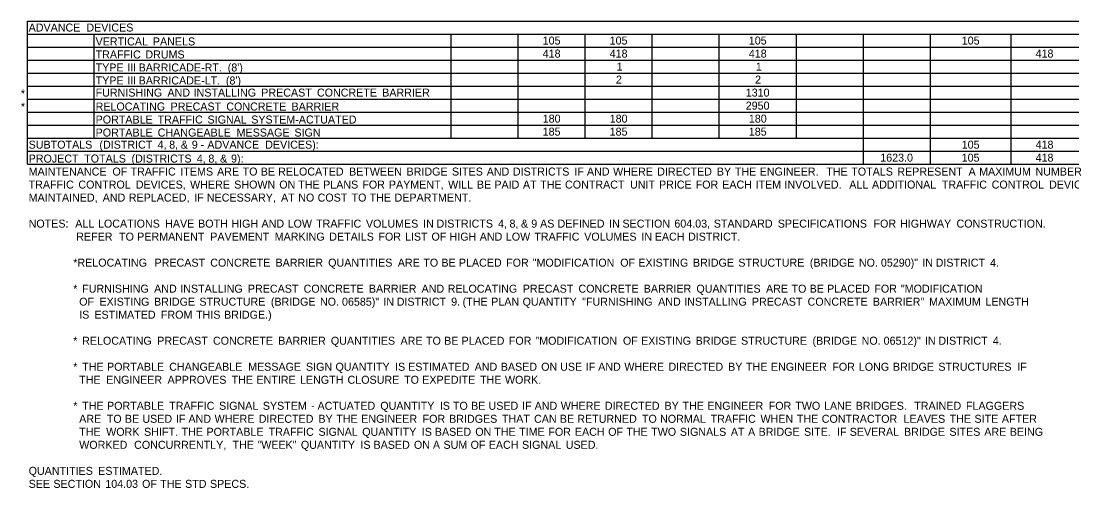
# Model space of a CAD drawing. Extents: x 544420 to 1930787, y -1947044 to 596640.
# Drawn here: x 544421 to 545209, y -1946986 to -1946636 of the extents above; entities that cross this region are included whole.
import ezdxf

# ---------------------------------------------------------------- set-up
doc = ezdxf.new("R2010")
doc.units = 0
doc.layers.add('Default', color=7, linetype='Continuous')

msp = doc.modelspace()

# ---------------------------------------------------------------- linework, layer by layer
at = {"layer": 'Default'}
for p, q in [((544425.9, -1946636.01), (545626.13, -1946636.01)), ((544425.9, -1946636.01), (545626.13, -1946636.01)), ((544425.9, -1946743.26), (544425.9, -1946636.01)), ((544425.9, -1946743.26), (544425.9, -1946636.01)), ((544425.9, -1946645.76), (545626.13, -1946645.76)), ((544476.12, -1946684.76), (544476.12, -1946645.76)), ((544476.12, -1946723.76), (544476.12, -1946645.76)), ((544743.75, -1946723.76), (544743.75, -1946645.76)), ((544743.75, -1946723.76), (544743.75, -1946645.76)), ((544793.97, -1946723.76), (544793.97, -1946645.76)), ((544793.97, -1946723.76), (544793.97, -1946645.76)), ((544844.18, -1946723.76), (544844.18, -1946645.76)), ((544844.18, -1946723.76), (544844.18, -1946645.76)), ((544894.39, -1946723.76), (544894.39, -1946645.76)), ((544894.39, -1946723.76), (544894.39, -1946645.76)), ((544944.6, -1946723.76), (544944.6, -1946645.76)), ((544944.6, -1946723.76), (544944.6, -1946645.76)), ((545002.62, -1946723.76), (545002.62, -1946645.76)), ((545052.83, -1946743.26), (545052.83, -1946645.76)), ((545052.83, -1946743.26), (545052.83, -1946645.76)), ((545103.04, -1946743.26), (545103.04, -1946645.76)), ((545103.04, -1946743.26), (545103.04, -1946645.76)), ((545163.49, -1946743.26), (545163.49, -1946645.76)), ((545163.49, -1946743.26), (545163.49, -1946645.76)), ((544425.9, -1946655.51), (545626.13, -1946655.51)), ((544425.9, -1946665.26), (545626.13, -1946665.26)), ((544425.9, -1946675.01), (545626.13, -1946675.01)), ((544425.9, -1946684.76), (545626.13, -1946684.76)), ((544425.9, -1946694.51), (544476.12, -1946694.51)), ((544425.9, -1946694.51), (545626.13, -1946694.51)), ((544476.12, -1946723.76), (544476.12, -1946694.51)), ((544743.75, -1946694.51), (544944.6, -1946694.51)), ((544944.6, -1946694.51), (545002.62, -1946694.51)), ((545002.62, -1946694.51), (545310.23, -1946694.51)), ((544425.9, -1946704.26), (545626.13, -1946704.26)), ((544425.9, -1946714.01), (545626.13, -1946714.01)), ((545002.62, -1946723.76), (545002.62, -1946714.01)), ((544425.9, -1946723.76), (545002.62, -1946723.76)), ((544425.9, -1946723.76), (545626.13, -1946723.76)), ((545002.62, -1946723.76), (545626.13, -1946723.76)), ((544425.9, -1946733.51), (545626.13, -1946733.51)), ((544425.9, -1946743.26), (545626.13, -1946743.26))]:
    msp.add_line(p, q, dxfattribs=at)

# ---------------------------------------------------------------- texts
for s, p in [('ADVANCE', (544426.88, -1946643.88)), (' DEVICES', (544467.92, -1946643.88)), ('105', (544812.25, -1946653.63)), ('105', (544862.46, -1946653.63)), ('105', (544966.79, -1946653.63)), ('105', (545126.44, -1946653.63)), ('VERTICAL', (544477.09, -1946654.31)), (' PANELS', (544517.79, -1946654.31)), ('TRAFFIC', (544477.09, -1946664.06)), (' DRUMS', (544512.15, -1946664.06)), ('418', (544812.27, -1946663.38)), ('418', (544862.48, -1946663.38)), ('418', (544966.81, -1946663.38)), ('418', (545181.79, -1946663.38)), ('TYPE', (544477.09, -1946673.81)), (' III', (544498.54, -1946673.81)), (' BARRICADE-RT.', (544507.11, -1946673.81)), (" (8')", (544573.91, -1946673.81)), ('1', (544867.73, -1946673.13)), ('1', (544972.05, -1946673.13)), ('TYPE', (544477.09, -1946683.56)), (' III', (544498.54, -1946683.56)), (' BARRICADE-LT.', (544507.11, -1946683.56)), (" (8')", (544572.52, -1946683.56)), ('2', (544867.18, -1946682.88)), ('2', (544971.5, -1946682.88)), ('*', (544421.03, -1946693.31)), ('FURNISHING', (544477.09, -1946692.63)), (' AND', (544528.73, -1946692.63)), (' INSTALLING', (544548.31, -1946692.63)), (' PRECAST', (544599.03, -1946692.63)), (' CONCRETE', (544640.79, -1946692.63)), (' BARRIER', (544689.72, -1946692.63)), ('1310', (544964.49, -1946692.63)), ('*', (544421.03, -1946703.06)), ('RELOCATING', (544477.09, -1946703.06)), (' PRECAST', (544531.07, -1946703.06)), (' CONCRETE', (544572.83, -1946703.06)), (' BARRIER', (544621.76, -1946703.06)), ('2950', (544964.49, -1946702.38)), ('PORTABLE', (544477.09, -1946712.81)), (' TRAFFIC', (544521.37, -1946712.81)), (' SIGNAL', (544558.76, -1946712.81)), (' SYSTEM-ACTUATED', (544591.54, -1946712.81)), ('180', (544812.28, -1946712.13)), ('180', (544862.5, -1946712.13)), ('180', (544966.82, -1946712.13)), ('PORTABLE', (544477.09, -1946722.56)), (' CHANGEABLE', (544521.37, -1946722.56)), (' MESSAGE', (544580.56, -1946722.56)), (' SIGN', (544623.91, -1946722.56)), ('185', (544812.25, -1946721.88)), ('185', (544862.46, -1946721.88)), ('185', (544966.79, -1946721.88)), ('SUBTOTALS', (544426.88, -1946731.63)), (' (DISTRICT', (544477.71, -1946731.63)), (' 4,', (544521.31, -1946731.63)), (' 8,', (544530.02, -1946731.63)), (' &', (544538.73, -1946731.63)), (' 9', (544546.98, -1946731.63)), (' ADVANCE', (544558.63, -1946731.63)), (' DEVICES):', (544602, -1946731.63)), ('105', (545126.4, -1946731.63)), ('418', (545181.8, -1946731.63)), (' -', (544553.57, -1946731.63)), ('PROJECT', (544426.88, -1946742.06)), (' TOTALS', (544466.3, -1946742.06)), (' (DISTRICTS', (544501.76, -1946742.06)), (' 4,', (544550.71, -1946742.06)), (' 8,', (544559.42, -1946742.06)), (' &', (544568.14, -1946742.06)), (' 9):', (544576.38, -1946742.06)), ('1623.0', (545065.33, -1946741.38)), ('105', (545126.4, -1946741.38)), ('418', (545181.8, -1946741.38)), ('MAINTENANCE', (544426.88, -1946751.81)), (' OF', (544487.46, -1946751.81)), (' TRAFFIC', (544501.04, -1946751.81)), (' ITEMS', (544538.43, -1946751.81)), (' ARE', (544565.94, -1946751.81)), (' TO', (544585.06, -1946751.81)), (' BE', (544598.66, -1946751.81)), (' RELOCATED', (544611.72, -1946751.81)), (' BETWEEN', (544664.85, -1946751.81)), (' BRIDGE', (544707.95, -1946751.81)), (' SITES', (544741.98, -1946751.81)), (' AND', (544768.09, -1946751.81)), (' DISTRICTS', (544787.67, -1946751.81)), (' IF', (544833.81, -1946751.81)), (' AND', (544843.21, -1946751.81)), (' WHERE', (544862.79, -1946751.81)), (' DIRECTED', (544895.88, -1946751.81)), (' BY', (544940.61, -1946751.81)), (' THE', (544954.06, -1946751.81)), (' ENGINEER.', (544972.71, -1946751.81)), ('  THE', (545020.43, -1946751.81)), (' TOTALS', (545041.4, -1946751.81)), (' REPRESENT', (545075.9, -1946751.81)), (' A', (545129.31, -1946751.81)), (' MAXIMUM', (545137.25, -1946751.81)), (' NUMBER', (545179.46, -1946751.81)), ('TRAFFIC', (544426.88, -1946761.56)), (' CONTROL', (544461.94, -1946761.56)), (' DEVICES,', (544504.96, -1946761.56)), (' WHERE', (544545.68, -1946761.56)), (' SHOWN', (544578.77, -1946761.56)), (' ON', (544612.55, -1946761.56)), (' THE', (544626.76, -1946761.56)), (' PLANS', (544645.41, -1946761.56)), (' FOR', (544674.8, -1946761.56)), (' PAYMENT,', (544694.71, -1946761.56)), (' WILL', (544739.15, -1946761.56)), (' BE', (544760.74, -1946761.56)), (' PAID', (544773.8, -1946761.56)), (' AT', (544795.25, -1946761.56)), (' THE', (544808.13, -1946761.56)), (' CONTRACT', (544826.78, -1946761.56)), (' UNIT', (544875.51, -1946761.56)), (' PRICE', (544897.23, -1946761.56)), (' FOR', (544924.73, -1946761.56)), (' EACH', (544944.64, -1946761.56)), (' ITEM', (544969.59, -1946761.56)), (' INVOLVED.', (544991.31, -1946761.56)), ('  ALL', (545037.64, -1946761.56)), (' ADDITIONAL', (545056.91, -1946761.56)), (' TRAFFIC', (545109.25, -1946761.56)), (' CONTROL', (545146.64, -1946761.56)), (' DEVICES', (545189.66, -1946761.56)), ('MAINTAINED,', (544426.88, -1946771.31)), (' AND', (544480.17, -1946771.31)), (' REPLACED,', (544499.75, -1946771.31)), (' IF', (544548.85, -1946771.31)), (' NECESSARY,', (544558.25, -1946771.31)), (' AT', (544613.88, -1946771.31)), (' NO', (544626.75, -1946771.31)), (' COST', (544641.28, -1946771.31)), (' TO', (544666.73, -1946771.31)), (' THE', (544680.33, -1946771.31)), (' DEPARTMENT.', (544698.98, -1946771.31)), ('NOTES:', (544426.88, -1946790.81)), ('  ALL', (544457.36, -1946790.81)), (' LOCATIONS', (544476.63, -1946790.81)), (' HAVE', (544526.97, -1946790.81)), (' BOTH', (544551.68, -1946790.81)), (' HIGH', (544576.62, -1946790.81)), (' AND', (544599.23, -1946790.81)), (' LOW', (544618.81, -1946790.81)), (' TRAFFIC', (544640.14, -1946790.81)), (' VOLUMES', (544677.53, -1946790.81)), (' IN', (544720.42, -1946790.81)), (' DISTRICTS', (544730.44, -1946790.81)), (' 4,', (544776.58, -1946790.81)), (' 8,', (544785.15, -1946790.81)), (' &', (544793.72, -1946790.81)), (' 9', (544801.45, -1946790.81)), (' AS', (544808.07, -1946790.81)), (' DEFINED', (544821.14, -1946790.81)), (' IN', (544859.82, -1946790.81)), (' SECTION', (544869.85, -1946790.81)), (' 604.03,', (544908.75, -1946790.81)), (' STANDARD', (544938.29, -1946790.81)), (' SPECIFICATIONS', (544986.29, -1946790.81)), (' FOR', (545058.06, -1946790.81)), (' HIGHWAY', (545077.97, -1946790.81)), (' CONSTRUCTION.', (545120.29, -1946790.81)), ('                REFER', (544426.88, -1946800.56)), (' TO', (544492.43, -1946800.56)), (' PERMANENT', (544506.02, -1946800.56)), (' PAVEMENT', (544560.82, -1946800.56)), (' MARKING', (544609.11, -1946800.56)), (' DETAILS', (544650.04, -1946800.56)), (' FOR', (544686.87, -1946800.56)), (' LIST', (544706.78, -1946800.56)), (' OF', (544726.64, -1946800.56)), (' HIGH', (544740.23, -1946800.56)), (' AND', (544762.84, -1946800.56)), (' LOW', (544782.42, -1946800.56)), (' TRAFFIC', (544803.74, -1946800.56)), (' VOLUMES', (544841.14, -1946800.56)), (' IN', (544884.02, -1946800.56)), (' EACH', (544894.05, -1946800.56)), (' DISTRICT.', (544918.99, -1946800.56)), ('               *RELOCATING', (544426.88, -1946820.06)), (' PRECAST', (544519.03, -1946820.06)), (' CONCRETE', (544560.8, -1946820.06)), (' BARRIER', (544609.72, -1946820.06)), (' QUANTITIES', (544649.21, -1946820.06)), (' ARE', (544701.41, -1946820.06)), (' TO', (544720.53, -1946820.06)), (' BE', (544734.12, -1946820.06)), (' PLACED', (544747.19, -1946820.06)), (' FOR', (544782.62, -1946820.06)), (' "MODIFICATION', (544802.53, -1946820.06)), (' OF', (544868.16, -1946820.06)), (' EXISTING', (544881.74, -1946820.06)), (' BRIDGE', (544922.68, -1946820.06)), (' STRUCTURE', (544956.7, -1946820.06)), (' (BRIDGE', (545010.29, -1946820.06)), (' NO.', (545047.1, -1946820.06)), (' 05290)"', (545063.6, -1946820.06)), (' IN', (545094.6, -1946820.06)), (' DISTRICT', (545104.63, -1946820.06)), (' 4.', (545145.44, -1946820.06)), ('               *', (544426.88, -1946839.56)), (' FURNISHING', (544464.76, -1946839.56)), (' AND', (544518.73, -1946839.56)), (' INSTALLING', (544538.31, -1946839.56)), (' PRECAST', (544589.03, -1946839.56)), (' CONCRETE', (544630.79, -1946839.56)), (' BARRIER', (544679.72, -1946839.56)), (' AND', (544719.21, -1946839.56)), (' RELOCATING', (544738.79, -1946839.56)), (' PRECAST', (544795.09, -1946839.56)), (' CONCRETE', (544836.85, -1946839.56)), (' BARRIER', (544885.78, -1946839.56)), (' QUANTITIES', (544925.27, -1946839.56)), (' ARE', (544977.47, -1946839.56)), (' TO', (544996.59, -1946839.56)), (' BE', (545010.18, -1946839.56)), (' PLACED', (545023.25, -1946839.56)), (' FOR', (545058.68, -1946839.56)), (' "MODIFICATION', (545078.59, -1946839.56)), ('                 OF', (544426.88, -1946849.31)), (' EXISTING', (544477.71, -1946849.31)), (' BRIDGE', (544518.64, -1946849.31)), (' STRUCTURE', (544552.67, -1946849.31)), (' (BRIDGE', (544606.25, -1946849.31)), (' NO.', (544643.07, -1946849.31)), (' 06585)"', (544659.57, -1946849.31)), (' IN', (544690.57, -1946849.31)), (' DISTRICT', (544700.59, -1946849.31)), (' 9.', (544741.41, -1946849.31)), (' (THE', (544749.99, -1946849.31)), (' PLAN', (544771.43, -1946849.31)), (' QUANTITY', (544794.97, -1946849.31)), (' "FURNISHING', (544839.63, -1946849.31)), (' AND', (544896.57, -1946849.31)), (' INSTALLING', (544916.15, -1946849.31)), (' PRECAST', (544966.87, -1946849.31)), (' CONCRETE', (545008.63, -1946849.31)), (' BARRIER"', (545057.56, -1946849.31)), (' MAXIMUM', (545099.74, -1946849.31)), (' LENGTH', (545141.96, -1946849.31)), (' BRIDGE.)', (544571.16, -1946859.06)), ('                 IS', (544426.88, -1946859.06)), (' ESTIMATED', (544473.93, -1946859.06)), (' FROM', (544523.79, -1946859.06)), (' THIS', (544550.17, -1946859.06)), ('               *', (544426.88, -1946878.56)), (' RELOCATING', (544464.76, -1946878.56)), (' PRECAST', (544521.07, -1946878.56)), (' CONCRETE', (544562.83, -1946878.56)), (' BARRIER', (544611.76, -1946878.56)), (' QUANTITIES', (544651.24, -1946878.56)), (' ARE', (544703.44, -1946878.56)), (' TO', (544722.56, -1946878.56)), (' BE', (544736.16, -1946878.56)), (' PLACED', (544749.22, -1946878.56)), (' FOR', (544784.65, -1946878.56)), (' "MODIFICATION', (544804.56, -1946878.56)), (' OF', (544870.19, -1946878.56)), (' EXISTING', (544883.78, -1946878.56)), (' BRIDGE', (544924.71, -1946878.56)), (' STRUCTURE', (544958.74, -1946878.56)), (' (BRIDGE', (545012.32, -1946878.56)), (' NO.', (545049.14, -1946878.56)), (' 06512)"', (545065.64, -1946878.56)), (' IN', (545096.64, -1946878.56)), (' DISTRICT', (545106.66, -1946878.56)), (' 4.', (545147.48, -1946878.56)), ('               *', (544426.88, -1946898.06)), (' THE', (544464.76, -1946898.06)), (' PORTABLE', (544483.41, -1946898.06)), (' CHANGEABLE', (544530.02, -1946898.06)), (' MESSAGE', (544589.21, -1946898.06)), (' SIGN', (544632.56, -1946898.06)), (' QUANTITY', (544654.7, -1946898.06)), (' IS', (544699.35, -1946898.06)), (' ESTIMATED', (544709.16, -1946898.06)), (' AND', (544759.02, -1946898.06)), (' BASED', (544778.61, -1946898.06)), (' ON', (544808.91, -1946898.06)), (' USE', (544823.13, -1946898.06)), (' IF', (544842.25, -1946898.06)), (' AND', (544851.64, -1946898.06)), (' WHERE', (544871.23, -1946898.06)), (' DIRECTED', (544904.31, -1946898.06)), (' BY', (544949.05, -1946898.06)), (' THE', (544962.5, -1946898.06)), (' ENGINEER', (544981.15, -1946898.06)), (' FOR', (545027.15, -1946898.06)), (' LONG', (545047.06, -1946898.06)), (' BRIDGE', (545072.62, -1946898.06)), (' STRUCTURES', (545106.65, -1946898.06)), (' IF', (545165.83, -1946898.06)), ('                 THE', (544426.88, -1946907.81)), (' ENGINEER', (544482.77, -1946907.81)), (' APPROVES', (544528.78, -1946907.81)), (' THE', (544576.8, -1946907.81)), (' ENTIRE', (544595.45, -1946907.81)), (' LENGTH', (544628.08, -1946907.81)), (' CLOSURE', (544663.73, -1946907.81)), (' TO', (544706.14, -1946907.81)), (' EXPEDITE', (544719.74, -1946907.81)), (' THE', (544763.09, -1946907.81)), (' WORK.', (544781.74, -1946907.81)), ('               *', (544426.88, -1946927.31)), (' THE', (544464.76, -1946927.31)), (' PORTABLE', (544483.41, -1946927.31)), (' TRAFFIC', (544530.02, -1946927.31)), (' SIGNAL', (544567.41, -1946927.31)), (' SYSTEM', (544600.19, -1946927.31)), (' ACTUATED', (544641.22, -1946927.31)), (' QUANTITY', (544688.29, -1946927.31)), (' IS', (544732.94, -1946927.31)), (' TO', (544742.75, -1946927.31)), (' BE', (544756.35, -1946927.31)), (' USED', (544769.41, -1946927.31)), (' IF', (544794.59, -1946927.31)), (' AND', (544803.98, -1946927.31)), (' WHERE', (544823.56, -1946927.31)), (' DIRECTED', (544856.65, -1946927.31)), (' BY', (544901.39, -1946927.31)), (' THE', (544914.84, -1946927.31)), (' ENGINEER', (544933.49, -1946927.31)), (' FOR', (544979.49, -1946927.31)), (' TWO', (544999.4, -1946927.31)), (' LANE', (545020.91, -1946927.31)), (' BRIDGES.', (545044.69, -1946927.31)), ('  TRAINED', (545086.35, -1946927.31)), (' FLAGGERS', (545127.36, -1946927.31)), ('                 ARE', (544426.88, -1946937.06)), (' TO', (544483.24, -1946937.06)), (' BE', (544496.84, -1946937.06)), (' USED', (544509.9, -1946937.06)), (' IF', (544535.08, -1946937.06)), (' AND', (544544.47, -1946937.06)), (' WHERE', (544564.06, -1946937.06)), (' DIRECTED', (544597.14, -1946937.06)), (' -', (544636.37, -1946927.31)), (' BY', (544641.88, -1946937.06)), (' THE', (544655.33, -1946937.06)), (' ENGINEER', (544673.98, -1946937.06)), (' FOR', (544719.98, -1946937.06)), (' BRIDGES', (544739.89, -1946937.06)), (' THAT', (544779.52, -1946937.06)), (' CAN', (544803.57, -1946937.06)), (' BE', (544822.92, -1946937.06)), (' RETURNED', (544835.98, -1946937.06)), (' TO', (544884.44, -1946937.06)), (' NORMAL', (544898.04, -1946937.06)), (' TRAFFIC', (544935.94, -1946937.06)), (' WHEN', (544973.33, -1946937.06)), (' THE', (545000.58, -1946937.06)), (' CONTRACTOR', (545019.23, -1946937.06)), (' LEAVES', (545080.6, -1946937.06)), (' THE', (545115.11, -1946937.06)), (' SITE', (545133.76, -1946937.06)), (' AFTER', (545154.28, -1946937.06)), ('                 THE', (544426.88, -1946946.81)), (' WORK', (544482.77, -1946946.81)), (' SHIFT.', (544511.16, -1946946.81)), (' THE', (544539.31, -1946946.81)), (' PORTABLE', (544557.96, -1946946.81)), (' TRAFFIC', (544604.56, -1946946.81)), (' SIGNAL', (544641.96, -1946946.81)), (' QUANTITY', (544674.74, -1946946.81)), (' IS', (544719.39, -1946946.81)), (' BASED', (544729.2, -1946946.81)), (' ON', (544759.5, -1946946.81)), (' THE', (544773.72, -1946946.81)), (' TIME', (544792.37, -1946946.81)), (' FOR', (544814.28, -1946946.81)), (' EACH', (544834.19, -1946946.81)), (' OF', (544859.14, -1946946.81)), (' THE', (544872.72, -1946946.81)), (' TWO', (544891.37, -1946946.81)), (' SIGNALS', (544912.88, -1946946.81)), (' AT', (544951.11, -1946946.81)), (' A', (544963.98, -1946946.81)), (' BRIDGE', (544971.92, -1946946.81)), (' SITE.', (545005.94, -1946946.81)), ('  IF', (545028.5, -1946946.81)), (' SEVERAL', (545040.22, -1946946.81)), (' BRIDGE', (545080.93, -1946946.81)), (' SITES', (545114.96, -1946946.81)), (' ARE', (545141.08, -1946946.81)), (' BEING', (545160.2, -1946946.81)), ('                 WORKED', (544426.88, -1946956.56)), (' CONCURRENTLY,', (544503.73, -1946956.56)), (' THE', (544577.51, -1946956.56)), (' "WEEK"', (544596.16, -1946956.56)), (' QUANTITY', (544628.74, -1946956.56)), (' IS', (544673.4, -1946956.56)), (' BASED', (544683.21, -1946956.56)), (' ON', (544713.51, -1946956.56)), (' A', (544727.73, -1946956.56)), (' SUM', (544735.66, -1946956.56)), (' OF', (544755.99, -1946956.56)), (' EACH', (544769.58, -1946956.56)), (' SIGNAL', (544794.53, -1946956.56)), (' USED.', (544827.31, -1946956.56)), ('QUANTITIES', (544426.88, -1946976.06)), (' ESTIMATED.', (544476.75, -1946976.06)), ('SEE', (544426.88, -1946985.81)), (' SECTION', (544443.21, -1946985.81)), (' 104.03', (544482.12, -1946985.81)), (' OF', (544509.69, -1946985.81)), (' THE', (544523.28, -1946985.81)), (' STD', (544541.93, -1946985.81)), (' SPECS.', (544560.58, -1946985.81))]:
    msp.add_text(s, height=6, dxfattribs=at).set_placement(p)

doc.saveas('drawing.dxf')
